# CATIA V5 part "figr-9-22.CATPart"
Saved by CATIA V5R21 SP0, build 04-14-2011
Part number: Part3
Bounding box of the stored display mesh (mm): x -112 to 0, y -101.683 to 104.654, z -80.304 to 44.557
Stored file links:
  D:\CATIA V5R21 E-RESOURCES\CATIA-V5R21\catia-v5r21-prt\c09-catia-v5r20-prt\c09-catia-v5r21-figr-9-22.CATPart
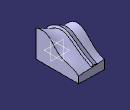
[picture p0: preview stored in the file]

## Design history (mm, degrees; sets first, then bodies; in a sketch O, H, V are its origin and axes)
Set1
  Plane1: type Offset, RefPlane yz-plane, Offset -112
  Plane2: type Offset, RefPlane yz-plane, Offset -63
  Plane3: type Normal, Curve Sketch4, RefPoint vertex of Sketch4
Body1 (main body)
  Sketch1 on yz-plane, origin (0, 0, 0), H (0, 1, 0), V (0, 0, 1)
    spline S1 through (-92.6897, 40.1119) (-30, 30) (10, -10) (60, -30) (97.3103, -50.3041)
    line L1 (97.3103, -50.3041) -> (97.3103, -80.3041)
    line L2 (97.3103, -80.3041) -> (-92.6897, -80.3041)
    line L3 (-92.6897, -80.3041) -> (-92.6897, 40.1119)
    point P3 (-92.6897, 40.1119)
    point P4 (97.3103, -50.3041)
    point P5 (-92.6897, 40.1119)
    point P6 (97.3103, -50.3041)
    vertical: L1 V, L3 V
    horizontal: L2 H
    coincidence: P5 P3, P6 P4
  Sketch2 on Plane1, origin (-112, 0, 0), H (0, 1, 0), V (0, 0, 1)
    spline S1 through (-90, -30) (-70, 10) (-20, 40) (40, 0) (100, -40)
    line L1 (100, -40) -> (100, -80)
    line L2 (100, -80) -> (-90, -80)
    line L3 (-90, -80) -> (-90, -30)
    point P3 (-90, -30)
    point P4 (100, -40)
    point P5 (40, 0)
    point P6 (-90, -30)
    point P7 (100, -40)
    coincidence: P5 H, P6 P3, P7 P4
    vertical: L1 V, L3 V
    horizontal: L2 H
  Loft1: Sections (Sketch1; Sketch2)
  Sketch3 on Plane3, origin (0, -40.1726, -44.9298), H (1, 0, 0), V (0, -0.7455, 0.6665)
    point P1 (-63, 68.4187)
    line L1 (-63, 68.4187) -> (-75.2117, 62.4925)
    line L2 (-75.2117, 62.4925) -> (-79.6266, 71.5898)
    line L3 (-79.6266, 71.5898) -> (-57.1205, 82.5119)
    line L4 (-57.1205, 82.5119) -> (-52.7056, 73.4145)
    point P5 (-52.7056, 73.4145)
    line L5 (-52.7056, 73.4145) -> (-63, 68.4187)
    reference projected point E1 (-63, 68.4187) from vertex of Sketch4
    perpendicularity: L2 L1
    parallelism: L3 L1, L4 L2, L5 L1
    coincidence: P5 L1, P1 E1
  Sketch4 on Plane2, origin (-63, 0, 0), H (0, 1, 0), V (0, 0, 1)
    intersected curve E1 from face of Loft1
  Rib1: profile Sketch3, centre curve Sketch4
